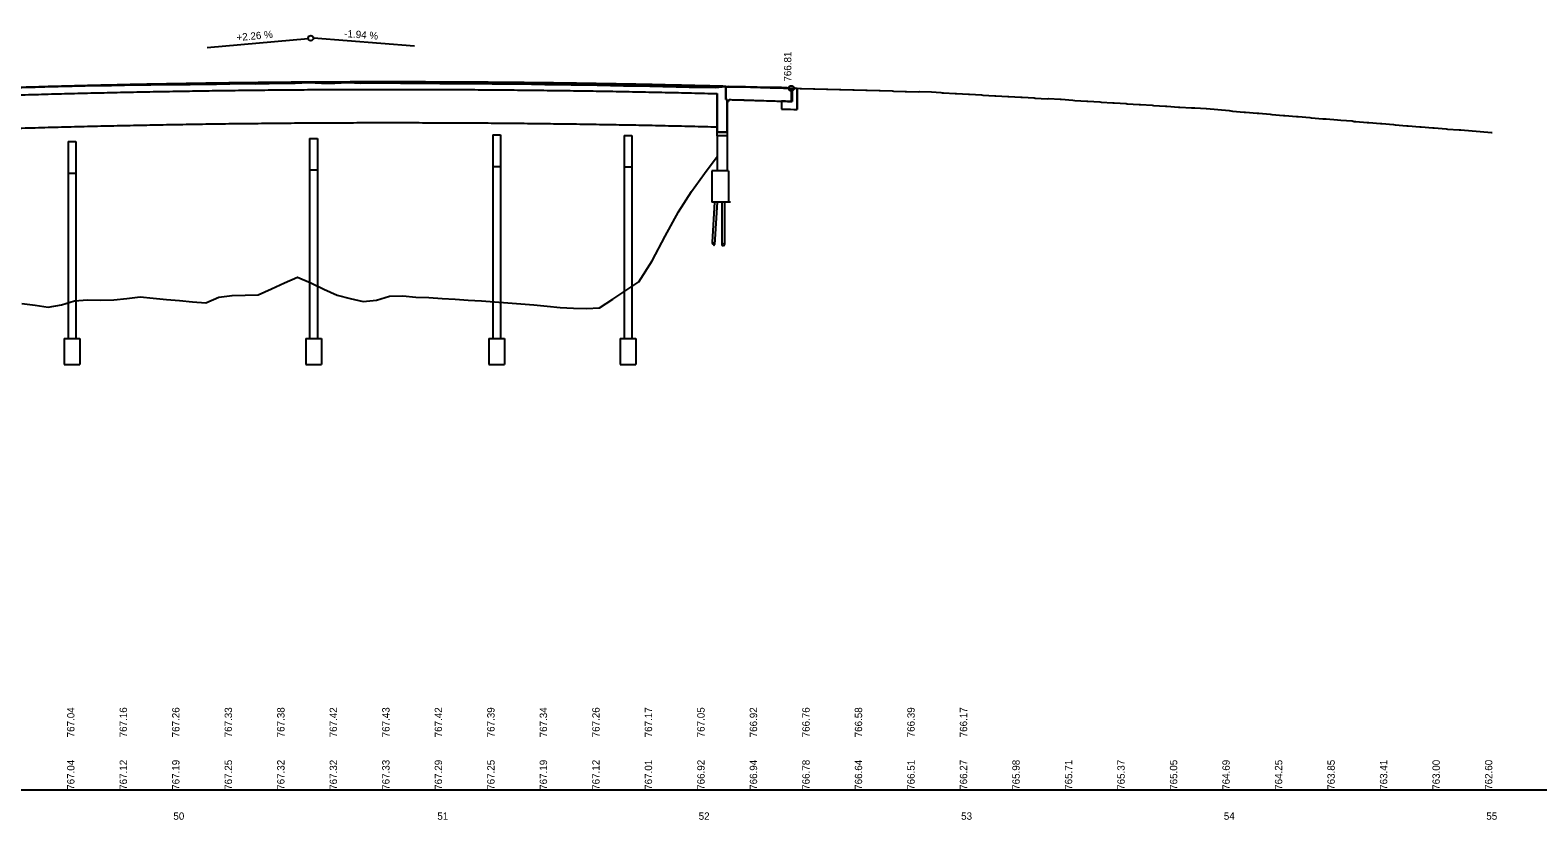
# Model space of a CAD drawing. Extents: x -209 to 3291, y 1080 to 3580.
# Drawn here: x 334 to 909, y 2069 to 2370 of the extents above; entities that cross this region are included whole.
import ezdxf

# ---------------------------------------------------------------- set-up
doc = ezdxf.new("R2010")
doc.units = 0
for name, color, linetype in [('BR_P_Gen_Approach_Slab', 7, 'Continuous'), ('BR_P_Gen_Approach_Slab_Hidden', 7, 'Continuous'), ('BR_P_Gen_Joint_Filler', 7, 'Continuous'), ('BR_P_Slab_Object', 7, 'Continuous'), ('BR_X_Sub_Foot_Object', 7, 'Continuous'), ('Default', 7, 'Continuous'), ('GK_Cells', 7, 'Continuous'), ('PF_P_Grade_Line', 7, 'Continuous'), ('PF_P_Sta_Elev_Text', 7, 'Continuous'), ('PF_P_Text', 7, 'Continuous'), ('PF_X_Ground_Line', 7, 'Continuous'), ('PF_X_Text', 7, 'Continuous')]:
    doc.layers.add(name, color=color, linetype=linetype)

msp = doc.modelspace()

# ---------------------------------------------------------------- linework, layer by layer
at = {"layer": 'BR_P_Gen_Approach_Slab'}
for p, q in [((600.33, 2342.45), (600.66, 2343.1)), ((624.33, 2342.41), (624.33, 2347.41)), ((624.33, 2347.41), (626.56, 2347.41)), ((624.55, 2347.41), (624.55, 2342.4)), ((626.56, 2347.41), (626.56, 2339.34)), ((599.83, 2342.46), (600.33, 2342.45)), ((620.54, 2342.53), (620.54, 2339.53))]:
    msp.add_line(p, q, dxfattribs=at)
for points in [[(600.66, 2343.1), (601.26, 2343.09), (611.26, 2342.81), (621.26, 2342.5), (624.55, 2342.4)], [(620.54, 2339.53), (621.25, 2339.5), (626.56, 2339.34)]]:
    msp.add_spline(points, degree=3, dxfattribs=at)
at = {"layer": 'BR_P_Gen_Approach_Slab_Hidden'}
msp.add_line((599.83, 2330.71), (596.07, 2330.71), dxfattribs=at)
at = {"layer": 'BR_P_Gen_Joint_Filler'}
for p, q in [((596.07, 2329.37), (596.07, 2330.71)), ((596.07, 2330.71), (599.83, 2330.71)), ((599.83, 2329.37), (596.07, 2329.37)), ((599.83, 2330.71), (599.83, 2329.37))]:
    msp.add_line(p, q, dxfattribs=at)
at = {"layer": 'BR_P_Slab_Object'}
for p, q in [((596.07, 2329.37), (596.07, 2345.39)), ((599.33, 2348.14), (599.33, 2343.13)), ((599.83, 2343.13), (599.33, 2343.13)), ((599.83, 2343.13), (599.83, 2329.37))]:
    msp.add_line(p, q, dxfattribs=at)
at = {"layer": 'BR_X_Sub_Foot_Object'}
for p, q in [((348.83, 2327.1), (351.83, 2327.1)), ((348.83, 2327.1), (348.83, 2315.1)), ((351.83, 2327.1), (351.83, 2315.1)), ((440.83, 2328.32), (443.83, 2328.32)), ((440.83, 2328.32), (440.83, 2316.32)), ((443.83, 2328.32), (443.83, 2316.32)), ((510.58, 2329.64), (513.58, 2329.64)), ((510.58, 2329.64), (510.58, 2317.64)), ((513.58, 2329.64), (513.58, 2317.64)), ((560.58, 2329.46), (563.58, 2329.46)), ((560.58, 2329.46), (560.58, 2317.46)), ((563.58, 2329.46), (563.58, 2317.46)), ((596.07, 2329.37), (596.07, 2316)), ((599.83, 2329.37), (596.07, 2329.37)), ((599.83, 2329.37), (599.83, 2316)), ((348.83, 2315.1), (351.83, 2315.1)), ((348.83, 2315.1), (348.83, 2252.13)), ((351.83, 2315.1), (351.83, 2252.13)), ((440.83, 2316.32), (443.83, 2316.32)), ((440.83, 2316.32), (440.83, 2252.13)), ((443.83, 2316.32), (443.83, 2252.13)), ((510.58, 2317.64), (513.58, 2317.64)), ((510.58, 2317.64), (510.58, 2252.13)), ((513.58, 2317.64), (513.58, 2252.13)), ((560.58, 2317.46), (563.58, 2317.46)), ((560.58, 2317.46), (560.58, 2252.13)), ((563.58, 2317.46), (563.58, 2252.13)), ((594.07, 2316), (594.07, 2304)), ((600.34, 2316), (594.07, 2316)), ((600.34, 2316), (600.34, 2304)), ((600.34, 2304), (594.07, 2304)), ((595.05, 2304), (594.11, 2288.84)), ((596.08, 2304), (595.08, 2287.87)), ((598.33, 2304), (597.33, 2304)), ((597.84, 2304), (597.84, 2287.88)), ((600.34, 2304), (598.34, 2304)), ((598.84, 2304), (598.84, 2287.88)), ((601.1, 2304), (600.1, 2304)), ((347.33, 2252.13), (347.33, 2242.13)), ((347.33, 2252.13), (353.33, 2252.13)), ((353.33, 2252.13), (353.33, 2242.13)), ((439.33, 2252.13), (439.33, 2242.13)), ((439.33, 2252.13), (445.33, 2252.13)), ((445.33, 2252.13), (445.33, 2242.13)), ((509.08, 2252.13), (509.08, 2242.13)), ((509.08, 2252.13), (515.08, 2252.13)), ((515.08, 2252.13), (515.08, 2242.13)), ((559.08, 2252.13), (559.08, 2242.13)), ((559.08, 2252.13), (565.08, 2252.13)), ((565.08, 2252.13), (565.08, 2242.13)), ((347.33, 2242.13), (353.33, 2242.13)), ((439.33, 2242.13), (445.33, 2242.13)), ((509.08, 2242.13), (515.08, 2242.13)), ((559.08, 2242.13), (565.08, 2242.13))]:
    msp.add_line(p, q, dxfattribs=at)
for centre, major_axis, start_param, end_param in [((594.4, 2289.43), (0, 1.32), 2.03501, 3.758218), ((594.78, 2287.28), (0, -1.32), 2.03501, 3.758218), ((594.89, 2288.95), (0, -1.32), 5.176603, 6.899811), ((598.09, 2288.73), (0, 1.32), 2.279989, 4.003197), ((598.59, 2287.02), (0, -1.32), 2.279989, 4.003197), ((598.59, 2288.73), (0, -1.32), 5.421581, 7.144789)]:
    msp.add_ellipse(centre, major_axis=major_axis, ratio=0.25, start_param=start_param, end_param=end_param, dxfattribs=at)
msp.add_spline([(286.83, 2330.74), (291.26, 2330.91), (301.26, 2331.28), (311.26, 2331.63), (321.26, 2331.96), (331.26, 2332.26), (341.26, 2332.55), (351.26, 2332.81), (361.26, 2333.06), (371.26, 2333.28), (381.26, 2333.48), (391.26, 2333.66), (401.26, 2333.82), (411.26, 2333.96), (421.26, 2334.07), (431.26, 2334.17), (441.26, 2334.24), (451.26, 2334.3), (461.26, 2334.33), (471.26, 2334.34), (481.26, 2334.33), (491.26, 2334.3), (501.26, 2334.25), (511.26, 2334.18), (521.26, 2334.09), (531.26, 2333.97), (541.26, 2333.84), (551.26, 2333.68), (561.26, 2333.51), (571.26, 2333.31), (581.26, 2333.09), (591.26, 2332.85), (596.07, 2332.73)], degree=3, dxfattribs=at)
at = {"layer": 'Default'}
for p, q in [((365.37, 2348.49), (370.37, 2348.6)), ((370.37, 2348.6), (375.37, 2348.77)), ((375.37, 2348.77), (380.37, 2348.71)), ((450.37, 2349.37), (455.37, 2349.64)), ((540.37, 2348.77), (545.37, 2348.71)), ((348.01, 2348.23), (350.37, 2348.25)), ((360.37, 2348.48), (365.37, 2348.49)), ((560.37, 2348.4), (565.37, 2348.3)), ((580.37, 2348), (585.37, 2347.87)), ((599.33, 2348.14), (599.15, 2348.15)), ((599.33, 2347.77), (599.33, 2343.13)), ((599.83, 2343.13), (599.33, 2343.13)), ((599.33, 2343.13), (599.83, 2343.13)), ((599.83, 2343.13), (599.83, 2342.46)), ((600.33, 2342.45), (600.66, 2343.1)), ((624.33, 2342.41), (624.33, 2346.41)), ((624.55, 2346.43), (624.55, 2342.4)), ((625.74, 2347.41), (625.33, 2347.41)), ((626.56, 2347.38), (625.74, 2347.41)), ((626.56, 2339.34), (626.56, 2347.38)), ((599.83, 2342.46), (600.33, 2342.45)), ((620.54, 2342.53), (620.54, 2339.53)), ((624.55, 2342.4), (624.33, 2342.41)), ((624.33, 2342.41), (624.33, 2342.41)), ((596.07, 2330.71), (599.83, 2330.71))]:
    msp.add_line(p, q, dxfattribs=at)
for points in [[(599.15, 2348.15), (595.37, 2347.75), (590.37, 2347.81), (585.37, 2347.87), (580.37, 2348), (575.37, 2348.12), (570.37, 2348.2), (565.37, 2348.3), (560.37, 2348.4), (555.37, 2348.52), (550.37, 2348.65), (545.37, 2348.71), (540.37, 2348.77), (535.37, 2348.86), (530.37, 2348.92), (525.37, 2348.97), (520.37, 2349.07), (515.37, 2349.11), (510.37, 2349.14), (505.37, 2349.19), (500.37, 2349.23), (495.37, 2349.27), (490.37, 2349.28), (485.37, 2349.36), (480.37, 2349.39), (475.37, 2349.39), (470.37, 2349.49), (465.37, 2349.45), (460.37, 2349.4), (455.37, 2349.64), (450.37, 2349.37), (445.37, 2349.32), (440.37, 2349.59), (435.37, 2349.42), (430.37, 2349.41), (425.37, 2349.29), (420.37, 2349.17), (415.37, 2349.23), (410.37, 2349.12), (405.37, 2349.01), (400.37, 2349.03), (395.37, 2348.87), (390.37, 2348.9), (385.37, 2348.9), (380.37, 2348.71), (375.37, 2348.77), (370.37, 2348.6), (365.37, 2348.49), (360.37, 2348.48), (355.37, 2348.4), (350.37, 2348.25), (348.01, 2348.23)], [(380.37, 2348.71), (385.37, 2348.9), (390.37, 2348.9), (395.37, 2348.87)], [(395.37, 2348.87), (400.37, 2349.03), (405.37, 2349.01), (410.37, 2349.12)], [(410.37, 2349.12), (415.37, 2349.23), (420.37, 2349.17), (425.37, 2349.29)], [(425.37, 2349.29), (430.37, 2349.41), (435.37, 2349.42)], [(435.37, 2349.42), (440.37, 2349.59), (445.37, 2349.32), (450.37, 2349.37)], [(455.37, 2349.64), (460.37, 2349.4), (465.37, 2349.45), (470.37, 2349.49), (475.37, 2349.39), (480.37, 2349.39), (485.37, 2349.36), (490.37, 2349.28)], [(490.37, 2349.28), (495.37, 2349.27), (500.37, 2349.23), (505.37, 2349.19)], [(505.37, 2349.19), (510.37, 2349.14), (515.37, 2349.11), (520.37, 2349.07), (525.37, 2348.97)], [(525.37, 2348.97), (530.37, 2348.92), (535.37, 2348.86), (540.37, 2348.77)], [(545.37, 2348.71), (550.37, 2348.65), (555.37, 2348.52), (560.37, 2348.4)], [(337.66, 2347.95), (335.37, 2347.86), (334.38, 2347.85)], [(350.37, 2348.25), (355.37, 2348.4), (360.37, 2348.48)], [(565.37, 2348.3), (570.37, 2348.2), (575.37, 2348.12), (580.37, 2348)], [(585.37, 2347.87), (590.37, 2347.81), (595.37, 2347.75), (599.15, 2348.15)], [(596.07, 2345.39), (596.07, 2332.73), (596.07, 2330.71)], [(599.33, 2343.13), (599.33, 2347.77), (599.33, 2348.14)], [(606.81, 2347.94), (603.38, 2347.96), (602.04, 2347.98), (599.59, 2347.87), (599.52, 2347.77), (599.33, 2347.77)], [(599.83, 2330.71), (599.83, 2342.46), (599.83, 2343.13)], [(624.33, 2342.41), (624.33, 2342.41)]]:
    msp.add_lwpolyline(points, dxfattribs=at)
for start, end in [(178.17646, 270), (282.66953, 0)]:
    msp.add_arc((624.33, 2347.41), 1, start, end, dxfattribs=at)
for points in [[(441.43, 2349.74), (441.26, 2349.74), (431.26, 2349.67), (421.26, 2349.57), (411.26, 2349.46), (401.26, 2349.32), (391.26, 2349.16), (381.26, 2348.98), (371.26, 2348.78), (361.26, 2348.56), (351.26, 2348.31), (348.01, 2348.23)], [(599.15, 2348.15), (591.26, 2348.35), (581.26, 2348.59), (571.26, 2348.81), (561.26, 2349.01), (551.26, 2349.18), (541.26, 2349.34), (531.26, 2349.47), (521.26, 2349.59), (511.26, 2349.68), (501.26, 2349.75), (491.26, 2349.8), (481.26, 2349.83), (471.26, 2349.84), (461.26, 2349.83), (451.26, 2349.8), (441.43, 2349.74)], [(286.83, 2343.41), (291.26, 2343.58), (301.26, 2343.95), (311.26, 2344.3), (321.26, 2344.62), (331.26, 2344.93), (341.26, 2345.22), (351.26, 2345.48), (361.26, 2345.72), (371.26, 2345.94), (381.26, 2346.14), (391.26, 2346.32), (401.26, 2346.48), (411.26, 2346.62), (421.26, 2346.74), (431.26, 2346.83), (441.26, 2346.91), (451.26, 2346.96), (461.26, 2347), (471.26, 2347.01), (481.26, 2347), (491.26, 2346.97), (501.26, 2346.92), (511.26, 2346.85), (521.26, 2346.75), (531.26, 2346.64), (541.26, 2346.51), (551.26, 2346.35), (561.26, 2346.17), (571.26, 2345.97), (581.26, 2345.76), (591.26, 2345.52), (596.07, 2345.39)], [(334.38, 2347.85), (331.26, 2347.76), (321.26, 2347.46), (311.26, 2347.13), (301.26, 2346.78), (300.38, 2346.75)], [(348.01, 2348.23), (341.26, 2348.05), (337.66, 2347.95)], [(623.33, 2347.44), (621.26, 2347.5), (611.26, 2347.81), (606.81, 2347.94)], [(624.33, 2342.41), (621.26, 2342.5), (620.54, 2342.53)], [(620.54, 2339.53), (621.25, 2339.5), (626.56, 2339.34)]]:
    msp.add_spline(points, degree=3, dxfattribs=at)
for points, degree in [([(600.66, 2343.1), (600.86, 2343.1), (601.06, 2343.09), (601.26, 2343.09), (604.59, 2343), (607.92, 2342.9), (611.26, 2342.81), (614.59, 2342.71), (617.92, 2342.61), (621.26, 2342.5)], 3), ([(621.26, 2342.5), (622.28, 2342.47), (623.31, 2342.44), (624.33, 2342.41)], 2)]:
    msp.add_open_spline(points, degree=degree, dxfattribs=at)
at = {"layer": 'GK_Cells'}
msp.add_line((-8.74, 2080.13), (3291.26, 2080.13), dxfattribs=at)
at = {"layer": 'PF_P_Grade_Line'}
for points in [[(258.57, 2345.06), (261.26, 2345.18), (271.26, 2345.61), (281.26, 2346.02), (291.26, 2346.41), (301.26, 2346.78), (311.26, 2347.13), (321.26, 2347.46), (331.26, 2347.76), (341.26, 2348.05), (351.26, 2348.31), (361.26, 2348.56), (371.26, 2348.78), (381.26, 2348.98), (391.26, 2349.16), (401.26, 2349.32), (411.26, 2349.46), (421.26, 2349.57), (431.26, 2349.67), (441.26, 2349.74), (451.26, 2349.8), (461.26, 2349.83), (471.26, 2349.84), (481.26, 2349.83), (491.26, 2349.8), (501.26, 2349.75), (511.26, 2349.68), (521.26, 2349.59), (531.26, 2349.47), (541.26, 2349.34), (551.26, 2349.18), (561.26, 2349.01), (571.26, 2348.81), (581.26, 2348.59), (591.26, 2348.35), (601.26, 2348.09), (611.26, 2347.81), (621.26, 2347.5), (624.33, 2347.41)], [(286.83, 2343.41), (291.26, 2343.58), (301.26, 2343.95), (311.26, 2344.3), (321.26, 2344.62), (331.26, 2344.93), (341.26, 2345.22), (351.26, 2345.48), (361.26, 2345.72), (371.26, 2345.94), (381.26, 2346.14), (391.26, 2346.32), (401.26, 2346.48), (411.26, 2346.62), (421.26, 2346.74), (431.26, 2346.83), (441.26, 2346.91), (451.26, 2346.96), (461.26, 2347), (471.26, 2347.01), (481.26, 2347), (491.26, 2346.97), (501.26, 2346.92), (511.26, 2346.85), (521.26, 2346.75), (531.26, 2346.64), (541.26, 2346.51), (551.26, 2346.35), (561.26, 2346.17), (571.26, 2345.97), (581.26, 2345.76), (591.26, 2345.52), (596.07, 2345.39)]]:
    msp.add_spline(points, degree=3, dxfattribs=at)
at = {"layer": 'PF_P_Text'}
for p, q in [((401.82, 2362.97), (440.26, 2366.44)), ((480.74, 2363.47), (442.25, 2366.46))]:
    msp.add_line(p, q, dxfattribs=at)
for centre in [(441.26, 2366.53), (624.33, 2347.41)]:
    msp.add_circle(centre, 1, dxfattribs=at)
at = {"layer": 'PF_X_Ground_Line'}
for points in [[(330.37, 2347.83), (335.37, 2347.86), (340.37, 2348.05), (345.37, 2348.2), (350.37, 2348.25), (355.37, 2348.4), (360.37, 2348.48), (365.37, 2348.49), (370.37, 2348.6), (375.37, 2348.77), (380.37, 2348.71), (385.37, 2348.9), (390.37, 2348.9), (395.37, 2348.87), (400.37, 2349.03), (405.37, 2349.01), (410.37, 2349.12), (415.37, 2349.23), (420.37, 2349.17), (425.37, 2349.29), (430.37, 2349.41), (435.37, 2349.42), (440.37, 2349.59), (445.37, 2349.32), (450.37, 2349.37), (455.37, 2349.64), (460.37, 2349.4), (465.37, 2349.45), (470.37, 2349.49), (475.37, 2349.39), (480.37, 2349.39), (485.37, 2349.36), (490.37, 2349.28), (495.37, 2349.27), (500.37, 2349.23), (505.37, 2349.19), (510.37, 2349.14), (515.37, 2349.11), (520.37, 2349.07), (525.37, 2348.97), (530.37, 2348.92), (535.37, 2348.86), (540.37, 2348.77), (545.37, 2348.71), (550.37, 2348.65), (555.37, 2348.52), (560.37, 2348.4), (565.37, 2348.3), (570.37, 2348.2), (575.37, 2348.12), (580.37, 2348), (585.37, 2347.87), (590.37, 2347.81), (595.37, 2347.75), (600.37, 2348.27), (600.37, 2348.27)], [(598.99, 2347.77), (599.52, 2347.77), (599.59, 2347.87), (602.04, 2347.98), (603.38, 2347.96), (611.08, 2347.91), (611.64, 2347.89), (620.52, 2347.84), (622.66, 2347.71), (624.49, 2347.5), (625.57, 2347.41), (627.69, 2347.35), (628.18, 2347.34), (632.69, 2347.22), (633.18, 2347.2), (637.69, 2347.08), (638.18, 2347.06), (642.69, 2346.94), (643.17, 2346.93), (647.69, 2346.8), (648.17, 2346.79), (652.69, 2346.67), (653.17, 2346.65), (657.69, 2346.53), (658.16, 2346.52), (662.69, 2346.39), (663.16, 2346.38), (667.69, 2346.26), (668.16, 2346.24), (672.69, 2346.12), (673.26, 2346.14), (677.67, 2346.02), (681.22, 2345.82), (681.73, 2345.75), (682.19, 2345.72), (686.73, 2345.46), (687.18, 2345.43), (691.73, 2345.18), (692.18, 2345.15), (696.73, 2344.89), (697.17, 2344.86), (701.73, 2344.61), (702.17, 2344.57), (706.73, 2344.32), (707.16, 2344.29), (711.73, 2344.03), (712.16, 2344), (716.73, 2343.75), (717.15, 2343.72), (721.73, 2343.46), (722.26, 2343.5), (726.72, 2343.25), (727.02, 2343.23), (731.46, 2342.95), (732.24, 2342.82), (736.8, 2342.53), (737.24, 2342.5), (741.79, 2342.21), (742.25, 2342.18), (746.77, 2341.89), (747.25, 2341.86), (751.76, 2341.57), (752.25, 2341.54), (756.75, 2341.25), (757.25, 2341.21), (761.74, 2340.93), (762.26, 2340.89), (766.73, 2340.61), (767.26, 2340.57), (771.72, 2340.28), (772.26, 2340.25), (776.71, 2339.96), (777.27, 2339.92), (778.02, 2339.94), (782.31, 2339.67), (782.44, 2339.66), (786.72, 2339.29), (790.99, 2338.93), (792.28, 2338.75), (796.71, 2338.37), (797.28, 2338.32)], [(797.28, 2338.32), (801.71, 2337.94), (802.28, 2337.9), (806.71, 2337.52), (807.28, 2337.47), (811.71, 2337.09), (812.28, 2337.04), (816.71, 2336.66), (817.28, 2336.62), (821.7, 2336.24), (822.27, 2336.19), (826.7, 2335.81), (827.27, 2335.76), (828.04, 2335.79), (832.33, 2335.43), (833.59, 2335.32), (837.89, 2334.96), (838.66, 2334.81), (839.22, 2334.77), (843.66, 2334.41), (844.21, 2334.37), (848.66, 2334), (849.21, 2333.96), (853.66, 2333.59), (854.2, 2333.55), (858.66, 2333.18), (859.2, 2333.14), (863.66, 2332.77), (864.19, 2332.73), (868.66, 2332.36), (869.18, 2332.32), (873.66, 2331.95), (874.18, 2331.91), (878.65, 2331.54), (879.31, 2331.55), (883.65, 2331.19), (886.61, 2330.94), (890.96, 2330.57), (891.26, 2330.52)], [(331.26, 2265.46), (336.26, 2264.75), (341.26, 2264.03), (346.26, 2264.97), (351.26, 2266.42), (356.26, 2266.77), (361.26, 2266.75), (366.26, 2266.82), (371.26, 2267.39), (376.26, 2267.93), (381.26, 2267.47), (386.26, 2267), (391.26, 2266.53), (396.26, 2266.07), (401.26, 2265.63), (406.26, 2267.85), (411.26, 2268.51), (416.26, 2268.63), (421.26, 2268.79), (426.26, 2271.03), (431.26, 2273.27), (436.26, 2275.49), (441.26, 2273.31), (446.26, 2270.92), (451.26, 2268.57), (456.26, 2267.36), (461.26, 2266.15), (466.26, 2266.74), (471.26, 2268.16), (476.26, 2268.4), (481.26, 2267.85), (486.26, 2267.65), (491.26, 2267.35), (496.26, 2267.05), (501.26, 2266.75), (506.26, 2266.4), (511.26, 2266.04), (516.26, 2265.67), (521.26, 2265.3), (526.26, 2264.94), (531.26, 2264.47), (536.26, 2263.95), (541.26, 2263.71), (546.26, 2263.49), (551.26, 2263.81), (556.26, 2267.08), (561.26, 2270.35), (566.26, 2273.63), (571.26, 2281.71), (576.26, 2291.03), (581.26, 2300.36), (586.26, 2308.15), (591.26, 2314.9), (596.07, 2321.41)]]:
    msp.add_lwpolyline(points, dxfattribs=at)

# ---------------------------------------------------------------- texts
at = {"layer": 'PF_P_Sta_Elev_Text'}
for s, p in [('50', (388.93, 2068.73)), ('51', (489.46, 2068.73)), ('52', (589, 2068.73)), ('53', (688.96, 2068.73)), ('54', (789.01, 2068.73)), ('55', (888.98, 2068.73))]:
    msp.add_text(s, height=2.8, dxfattribs=at).set_placement(p)
at = {"layer": 'PF_P_Text'}
for s, rotation, p in [('+2.26 %', 5.1655, (413.11, 2365.39)), ('-1.94 %', 355.56844, (453.92, 2366.96)), ('766.81', 90, (624.28, 2349.96)), ('767.04', 90, (351.26, 2100.13)), ('767.04', 90, (351.26, 2100.13)), ('767.16', 90, (371.26, 2100.13)), ('767.16', 90, (371.26, 2100.13)), ('767.26', 90, (391.26, 2100.13)), ('767.26', 90, (391.26, 2100.13)), ('767.33', 90, (411.26, 2100.13)), ('767.33', 90, (411.26, 2100.13)), ('767.38', 90, (431.26, 2100.13)), ('767.38', 90, (431.26, 2100.13)), ('767.42', 90, (451.26, 2100.13)), ('767.42', 90, (451.26, 2100.13)), ('767.43', 90, (471.26, 2100.13)), ('767.43', 90, (471.26, 2100.13)), ('767.42', 90, (491.26, 2100.13)), ('767.42', 90, (491.26, 2100.13)), ('767.39', 90, (511.26, 2100.13)), ('767.39', 90, (511.26, 2100.13)), ('767.34', 90, (531.26, 2100.13)), ('767.34', 90, (531.26, 2100.13)), ('767.26', 90, (551.26, 2100.13)), ('767.26', 90, (551.26, 2100.13)), ('767.17', 90, (571.26, 2100.13)), ('767.17', 90, (571.26, 2100.13)), ('767.05', 90, (591.26, 2100.13)), ('767.05', 90, (591.26, 2100.13)), ('766.92', 90, (611.26, 2100.13)), ('766.76', 90, (631.26, 2100.13)), ('766.58', 90, (651.26, 2100.13)), ('766.39', 90, (671.26, 2100.13)), ('766.17', 90, (691.26, 2100.13))]:
    msp.add_text(s, height=2.8, rotation=rotation, dxfattribs=at).set_placement(p)
at = {"layer": 'PF_X_Text'}
for s, p in [('767.04', (351.26, 2080.13)), ('767.12', (371.26, 2080.13)), ('767.19', (391.26, 2080.13)), ('767.25', (411.26, 2080.13)), ('767.32', (431.26, 2080.13)), ('767.32', (451.26, 2080.13)), ('767.33', (471.26, 2080.13)), ('767.29', (491.26, 2080.13)), ('767.25', (511.26, 2080.13)), ('767.19', (531.26, 2080.13)), ('767.12', (551.26, 2080.13)), ('767.01', (571.26, 2080.13)), ('766.92', (591.26, 2080.13)), ('766.94', (611.26, 2080.13)), ('766.78', (631.26, 2080.13)), ('766.64', (651.26, 2080.13)), ('766.51', (671.26, 2080.13)), ('766.27', (691.26, 2080.13)), ('765.98', (711.26, 2080.13)), ('765.71', (731.26, 2080.13)), ('765.37', (751.26, 2080.13)), ('765.05', (771.26, 2080.13)), ('764.69', (791.26, 2080.13)), ('764.25', (811.26, 2080.13)), ('763.85', (831.26, 2080.13)), ('763.41', (851.26, 2080.13)), ('763.00', (871.26, 2080.13)), ('762.60', (891.26, 2080.13))]:
    msp.add_text(s, height=2.8, rotation=90, dxfattribs=at).set_placement(p)

doc.saveas('drawing.dxf')
